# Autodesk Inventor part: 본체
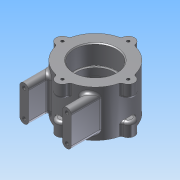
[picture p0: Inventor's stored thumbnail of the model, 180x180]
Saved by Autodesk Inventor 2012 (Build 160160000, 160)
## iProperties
Created: 2015-03
Part Number: 본체
Material: Default
Document SubType Name: Modeling
Designer: net
Density: 1 g/cm^3
Author: net
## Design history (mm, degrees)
sketch "스케치1"
  geometry: C1 r 37 at (0, 0); 1 further point
  constraints: 1 centre point, 1 coincident
  dimensions: "d0" = 74 diameter of C1
extrude "돌출1" new body sketch "스케치1" distance "d1" = 52; taper "d2" = 0 deg
sketch "스케치2"
  geometry: C1 r 7 at (0, 37); C2 r 7 at (-37, 0); C3 r 7 at (0, -37); C4 r 7 at (37, 0); 1 further point
  constraints: 4 centre point, 2 vertical alignment, 10 other
  dimensions: "d3" = 14 diameter of C1; "d6" = 360 deg dimension on point (0, 0) C1.centre (derived)
extrude "돌출2" join sketch "스케치2" distance "d8" = 15; taper "d9" = 0 deg
node "작업 평면1"
hole "구멍1" diameter "d12" = 42; stored, may be unused: countersink angle "d16" = 90 deg, drill point angle "d18" = 118 deg; dims "d10" = 10, "d11" = 10, "d13" = 6, "d14" = 47, "d15" = 22, "d17" = 8
hole "구멍2" diameter "d21" = 42; stored, may be unused: countersink angle "d25" = 90 deg, drill point angle "d27" = 118 deg; dims "d19" = 10, "d20" = 10, "d22" = 6, "d23" = 47, "d24" = 22, "d26" = 8
node "작업 평면2"
sketch "스케치4"
  geometry: L1 (6.969, 15)-(6.969, 0) reference; L2 (36.338, 0)-(6.969, 0) reference; L3 (36.338, 0)-(36.338, 15) reference; L4 (36.338, 15)-(36.338, 15) reference; L5 (36.338, 15)-(36.338, 0) reference; L6 (6.969, 0)-(36.338, 0) reference; L7 (6.969, 0)-(6.969, 15) reference; L8 (6.969, 15)-(-6.969, 15) reference; L9 (-6.969, 15)-(-6.969, 0) reference; L10 (-36.338, 0)-(-6.969, 0) reference; L11 (-36.338, 0)-(-36.338, 15) reference; L12 (-36.338, 15)-(-36.338, 15) reference; L13 (-36.338, 15)-(-36.338, 0) reference; L14 (-6.969, 0)-(-36.338, 0) reference; L15 (-6.969, 0)-(-6.969, 15) reference; L16 (-6.969, 15)-(6.969, 15) reference; L17 (6.969, 52)-(6.969, 37) reference; L18 (6.969, 37)-(-6.969, 37) reference; L19 (-6.969, 37)-(-6.969, 52) reference; L20 (-6.969, 52)-(-36.338, 52) reference; L21 (-36.338, 52)-(-36.338, 37) reference; L22 (-36.338, 37)-(-36.338, 37) reference; L23 (-36.338, 37)-(-36.338, 52) reference; L24 (-36.338, 52)-(-6.969, 52) reference; L25 (-6.969, 52)-(-6.969, 37) reference; L26 (-6.969, 37)-(6.969, 37) reference; L27 (6.969, 37)-(6.969, 52) reference; L28 (6.969, 52)-(36.338, 52) reference; L29 (36.338, 52)-(36.338, 37) reference; L30 (36.338, 37)-(36.338, 37) reference; L31 (36.338, 37)-(36.338, 52) reference; L32 (36.338, 52)-(6.969, 52) reference; L33 (0, 37)-(0, 15); L34 (0, 26)-(-24, 26); L35 (-24, 26)-(-24, 46); L36 (-24, 46)-(-24, 41); L37 (-24, 26)-(-24, 11); L38 (-19, 41)-(-19, 11); L39 (-29, 41)-(-29, 11); A1 r 5 centre (-24, 41) between (-19, 41) and (-29, 41); A2 r 5 centre (-24, 11) between (-19, 11) and (-29, 11); 1 further point
  constraints: 14 end point, 4 point on circle, 3 midpoint, 2 centre point, 2 coincident, 2 horizontal alignment, 2 perpendicular, 2 tangent, 1 collinear, 1 point on line
  dimensions: "d29" = 24 distance of L34.start L34.end; "d30" = 20 distance of L34.end L35.end; "d31" = 5 distance of L35.end L36.end; "d32" = 10 diameter of A1; "d33" = 15 distance of L34.end L37.end; "d34" = 10 diameter of A2; "d35" = 30 distance of L38.start L38.end
extrude "돌출3" join sketch "스케치4" stored distance "d36" = 15; taper "d37" = 0 deg
hole "구멍3" diameter "d40" = 3.242; stored, may be unused: countersink angle "d44" = 90 deg, drill point angle "d46" = 118 deg; dims "d38" = 10, "d39" = 10, "d41" = 8, "d42" = 47, "d43" = 22, "d45" = 11
node "작업 평면3"
sketch "스케치5"
  geometry: L1 (53, 30)-(53, 0) reference; L2 (43, 0)-(43, 30) reference; A1 r 5 centre (0, 0) between (-5, 0) and (5, 0) reference; A2 r 5 centre (0, 30) between (5, 30) and (-5, 30) reference; A3 r 5 centre (48, 0) between (43, 0) and (53, 0) reference; A4 r 5 centre (48, 30) between (53, 30) and (43, 30) reference; 5 further points
  constraints: 4 coincident
hole "구멍4" sketch "스케치5" at (0, 30), (0, 0), (48, 30), (48, 0) diameter "d50" = 4.134; stored, may be unused: countersink angle "d54" = 90 deg, drill point angle "d56" = 118 deg; dims "d51" = 6, "d52" = 47, "d53" = 22, "d55" = 8
node "작업 평면4"
sketch "스케치6"
  geometry: L1 (0, 0)-(-37, 0); L2 (0, 0)-(-26.163, 26.163); C1 r 1.621 at (37, 0) reference; C2 r 1.621 at (0, -37) reference; C3 r 1.621 at (-37, 0) reference; C4 r 1.621 at (0, 37) reference; C5 r 23.5 at (0, 0) reference; A1 r 37 centre (0, 0) between (36.338, 6.969) and (6.969, 36.338) reference; A2 r 7 centre (37, 0) between (36.338, -6.969) and (36.338, 6.969) reference; A3 r 37 centre (0, 0) between (6.969, -36.338) and (36.338, -6.969) reference; A4 r 7 centre (0, -37) between (-6.969, -36.338) and (6.969, -36.338) reference; A5 r 37 centre (0, 0) between (-36.338, -6.969) and (-6.969, -36.338) reference; A6 r 7 centre (-37, 0) between (-36.338, 6.969) and (-36.338, -6.969) reference; A7 r 37 centre (0, 0) between (-6.969, 36.338) and (-36.338, 6.969) reference; A8 r 7 centre (0, 37) between (6.969, 36.338) and (-6.969, 36.338) reference; 1 further point
  constraints: 4 end point, 1 horizontal, 1 point on circle
  dimensions: "d57" = 45 deg angle of L1 L2
  node "투영된 루프3"
node "작업 평면5"
sketch "스케치8"
  geometry: L1 (36.754, -15)-(36.754, 15) reference; L2 (35.885, 15)-(35.885, -15) reference; L3 (9.015, -15)-(9.015, 15) reference; L4 (-4.258, 15)-(-4.258, -15) reference; L5 (-20.767, -11)-(-20.767, -26) reference; L6 (20.767, -26)-(-20.767, -26) reference; L7 (20.767, -26)-(20.767, -11) reference; L8 (20.767, -11)-(30.622, -11) reference; L9 (30.622, -11)-(30.622, -26) reference; L10 (30.622, -26)-(30.622, -26) reference; L11 (30.622, -26)-(30.622, -11) reference; L12 (30.622, -11)-(20.767, -11) reference; L13 (20.767, -11)-(20.767, -26) reference; L14 (-20.767, -26)-(20.767, -26) reference; L15 (-20.767, -26)-(-20.767, -11) reference; L16 (-20.767, -11)-(-30.622, -11) reference; L17 (-30.622, -11)-(-30.622, -26) reference; L18 (-30.622, -26)-(-30.622, -26) reference; L19 (-30.622, -26)-(-30.622, -11) reference; L20 (-30.622, -11)-(-20.767, -11) reference; L21 (-20.767, 26)-(-20.767, 11) reference; L22 (-20.767, 11)-(-30.622, 11) reference; L23 (-30.622, 11)-(-30.622, 26) reference; L24 (-30.622, 26)-(-30.622, 26) reference; L25 (-30.622, 26)-(-30.622, 11) reference; L26 (-30.622, 11)-(-20.767, 11) reference; L27 (-20.767, 11)-(-20.767, 26) reference; L28 (-20.767, 26)-(20.767, 26) reference; L29 (20.767, 26)-(20.767, 11) reference; L30 (20.767, 11)-(30.622, 11) reference; L31 (30.622, 11)-(30.622, 26) reference; L32 (30.622, 26)-(30.622, 26) reference; L33 (30.622, 26)-(30.622, 11) reference; L34 (30.622, 11)-(20.767, 11) reference; L35 (20.767, 11)-(20.767, 26) reference; L36 (20.767, 26)-(-20.767, 26) reference; 3 further points
  constraints: 4 horizontal alignment, 1 other
feature "엠보싱1" sketch "스케치8" dims "d58" = 0.5, "d59" = 0
fillet "모깎기1" dims "d60" = 0.3
fillet "모깎기2" dims "d61" = 3
chamfer "모따기1" distance "d62" = 1; stored, may be unused: second distance "d63" = 2, angle "d64" = 45 deg
chamfer "모따기2" distance "d65" = 1; stored, may be unused: second distance "d66" = 2, angle "d67" = 45 deg
node "솔리드1"
mirror "대칭1"
mirror "대칭2"
pattern_circular "원형 패턴1" dims angle "d48" = 360 deg
mirror "대칭3"
node "투영된 루프1"
node "투영된 루프2"
node "투영된 루프4"
other parameters: "d28" = -56
